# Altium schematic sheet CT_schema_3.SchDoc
size 379 x 228 mm
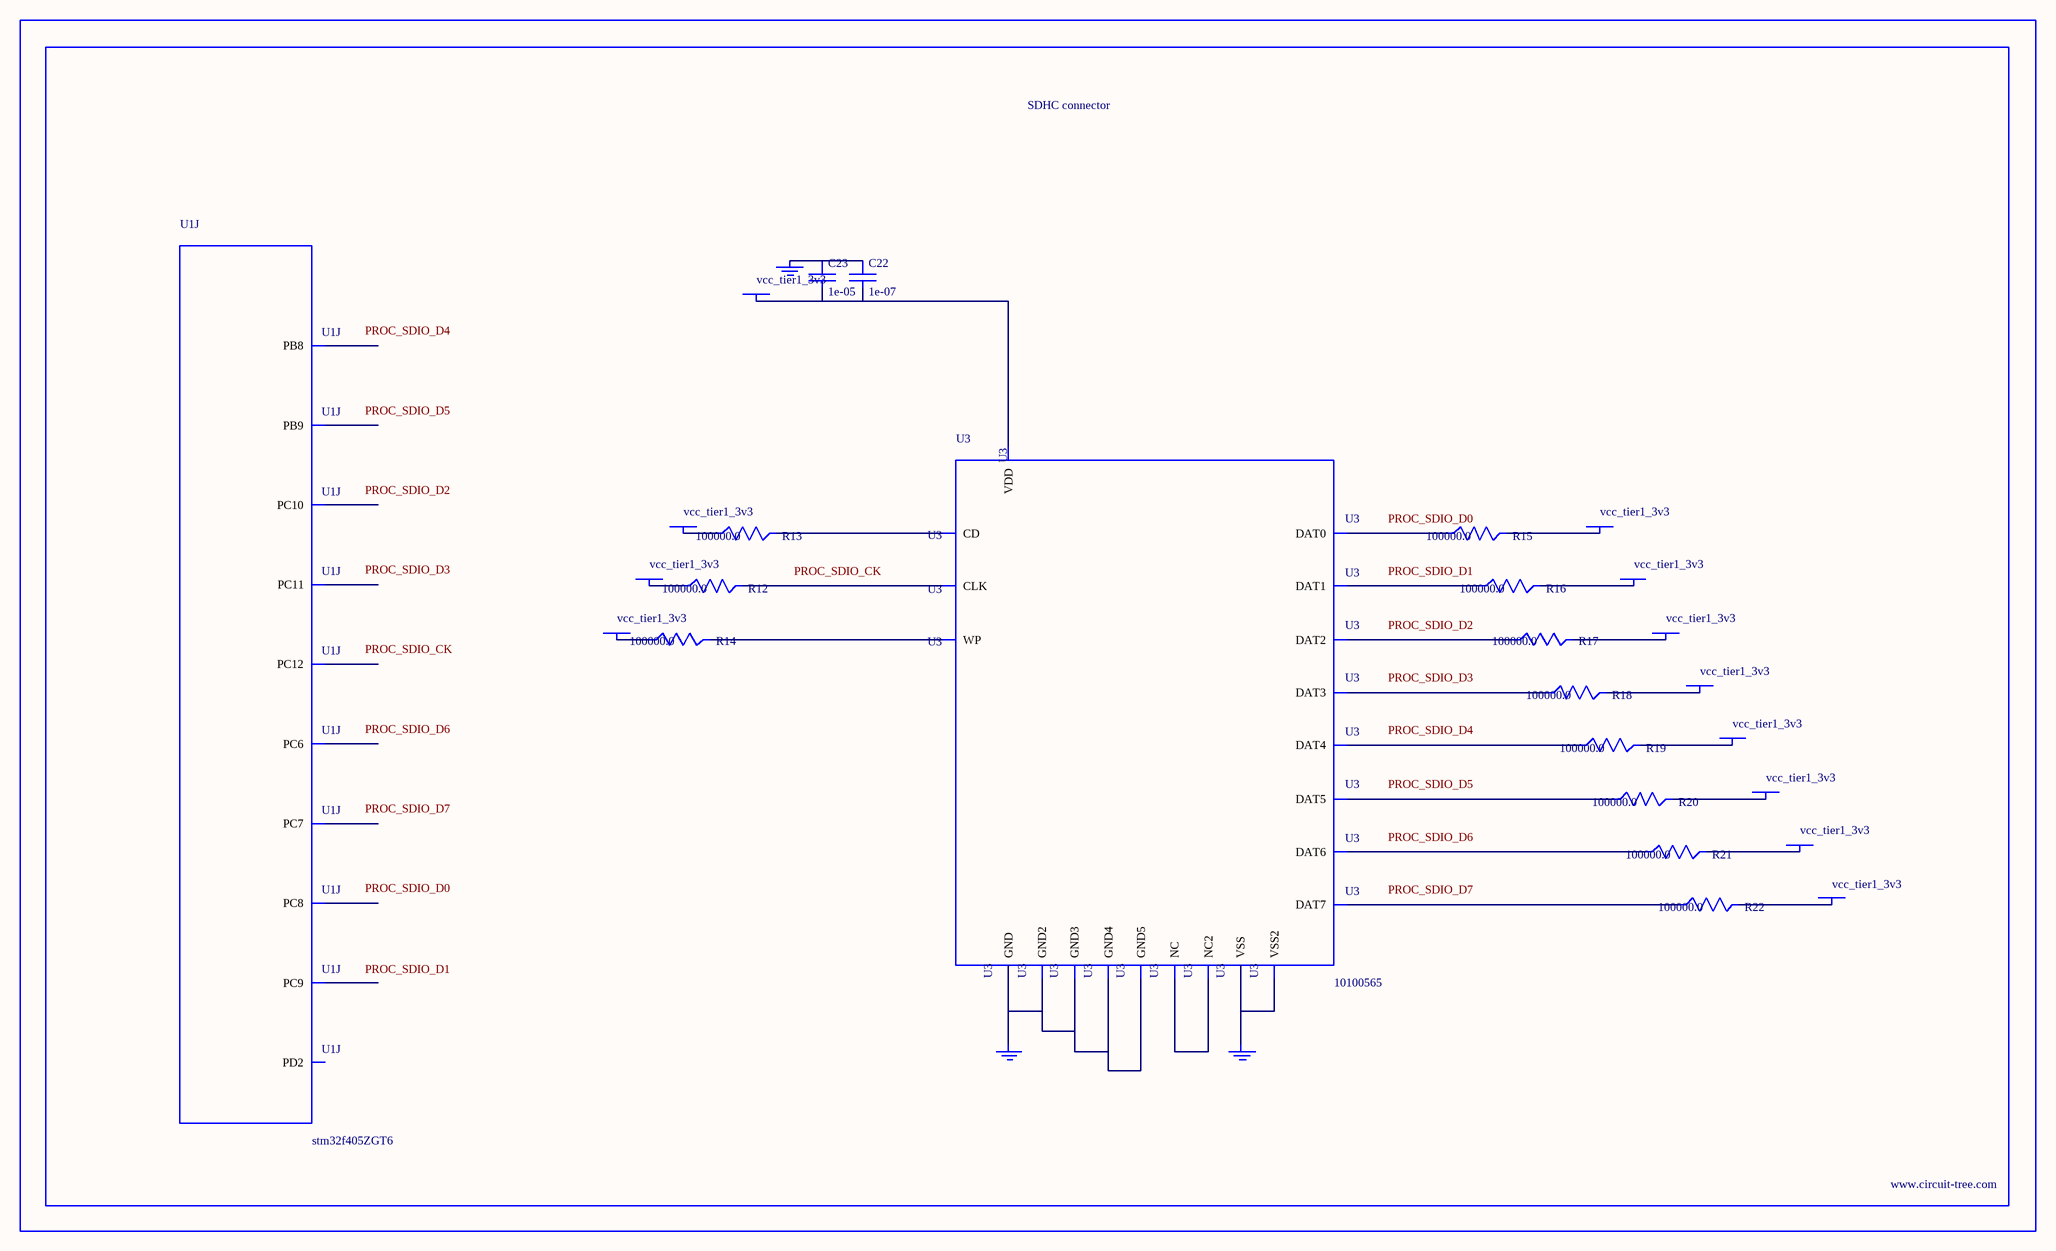
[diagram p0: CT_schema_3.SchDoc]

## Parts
BORDER2  (no value)
C22  1e-07  [C0402]
C23  1e-05  [C0805]
GND_INSTANCE_2_0  (no value)
GND_INSTANCE_2_1  (no value)
GND_INSTANCE_2_2  (no value)
POWER_INSTANCE_2_0  vcc_tier1_3v3
POWER_INSTANCE_2_1  vcc_tier1_3v3
POWER_INSTANCE_2_2  vcc_tier1_3v3
POWER_INSTANCE_2_3  vcc_tier1_3v3
POWER_INSTANCE_2_4  vcc_tier1_3v3
POWER_INSTANCE_2_5  vcc_tier1_3v3
POWER_INSTANCE_2_6  vcc_tier1_3v3
POWER_INSTANCE_2_7  vcc_tier1_3v3
POWER_INSTANCE_2_8  vcc_tier1_3v3
POWER_INSTANCE_2_9  vcc_tier1_3v3
POWER_INSTANCE_2_10  vcc_tier1_3v3
POWER_INSTANCE_2_11  vcc_tier1_3v3
R12  100000.0  [R0603]
R13  100000.0  [R0603]
R14  100000.0  [R0603]
R15  100000.0  [R0603]
R16  100000.0  [R0603]
R17  100000.0  [R0603]
R18  100000.0  [R0603]
R19  100000.0  [R0603]
R20  100000.0  [R0603]
R21  100000.0  [R0603]
R22  100000.0  [R0603]
U1  stm32f405ZGT6  [LQFP144]  (part J of 13)
U3  10100565  [10100565]

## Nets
NetC22_1: C22.1 C23.1 GND_INSTANCE_2_0.0(GND)
NetC22_2: C22.2 C23.2 POWER_INSTANCE_2_7.0(PWR) U3.9(VDD)
NetGND_INSTANCE_2_1_0: GND_INSTANCE_2_1.0(GND) U3.6(VSS) U3.10(VSS2)
NetGND_INSTANCE_2_2_0: GND_INSTANCE_2_2.0(GND) U3.12(GND) U3.16(GND2) U3.17(GND3) U3.20(GND4) U3.21(GND5)
NetPOWER_INSTANCE_2_0_0: POWER_INSTANCE_2_0.0(PWR) R14.1
NetPOWER_INSTANCE_2_1_0: POWER_INSTANCE_2_1.0(PWR) R13.1
NetPOWER_INSTANCE_2_2_0: POWER_INSTANCE_2_2.0(PWR) R16.2
NetPOWER_INSTANCE_2_3_0: POWER_INSTANCE_2_3.0(PWR) R15.2
NetPOWER_INSTANCE_2_4_0: POWER_INSTANCE_2_4.0(PWR) R22.2
NetPOWER_INSTANCE_2_5_0: POWER_INSTANCE_2_5.0(PWR) R21.2
NetPOWER_INSTANCE_2_6_0: POWER_INSTANCE_2_6.0(PWR) R12.1
NetPOWER_INSTANCE_2_8_0: POWER_INSTANCE_2_8.0(PWR) R20.2
NetPOWER_INSTANCE_2_9_0: POWER_INSTANCE_2_9.0(PWR) R19.2
NetPOWER_INSTANCE_2_10_0: POWER_INSTANCE_2_10.0(PWR) R18.2
NetPOWER_INSTANCE_2_11_0: POWER_INSTANCE_2_11.0(PWR) R17.2
NetR12_2: R12.2 U3.8(CLK)
NetR13_2: R13.2 U3.2(CD)
NetR14_2: R14.2 U3.1(WP)
NetR15_1: R15.1 U3.4(DAT0)
NetR16_1: R16.1 U3.3(DAT1)
NetR17_1: R17.1 U3.15(DAT2)
NetR18_1: R18.1 U3.14(DAT3)
NetR19_1: R19.1 U3.13(DAT4)
NetR20_1: R20.1 U3.11(DAT5)
NetR21_1: R21.1 U3.7(DAT6)
NetR22_1: R22.1 U3.5(DAT7)
NetU3_18: U3.18(NC) U3.19(NC2)

Not connected (* = marked no-connect by the designer): U1 96(PC6) 97(PC7) 98(PC8) 99(PC9) 111(PC10) 112(PC11) 113(PC12) 116(PD2) 139(PB8) 140(PB9)

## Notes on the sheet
- Labels drawn without touching a wire or pin: PROC_SDIO_CK, PROC_SDIO_D0, PROC_SDIO_D1, PROC_SDIO_D2, PROC_SDIO_D3, PROC_SDIO_D4, PROC_SDIO_D5, PROC_SDIO_D6, PROC_SDIO_D7

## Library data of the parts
BORDER2 = BORDER_PAGE2
C22 = C0402C104K3RACTU
C23 = C0805C106K8RACTU
GND_INSTANCE_2_0-GND_INSTANCE_2_2 = GND
POWER_INSTANCE_2_0-POWER_INSTANCE_2_11 = PWR
R12-R22 = RC0603JR-07100KL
